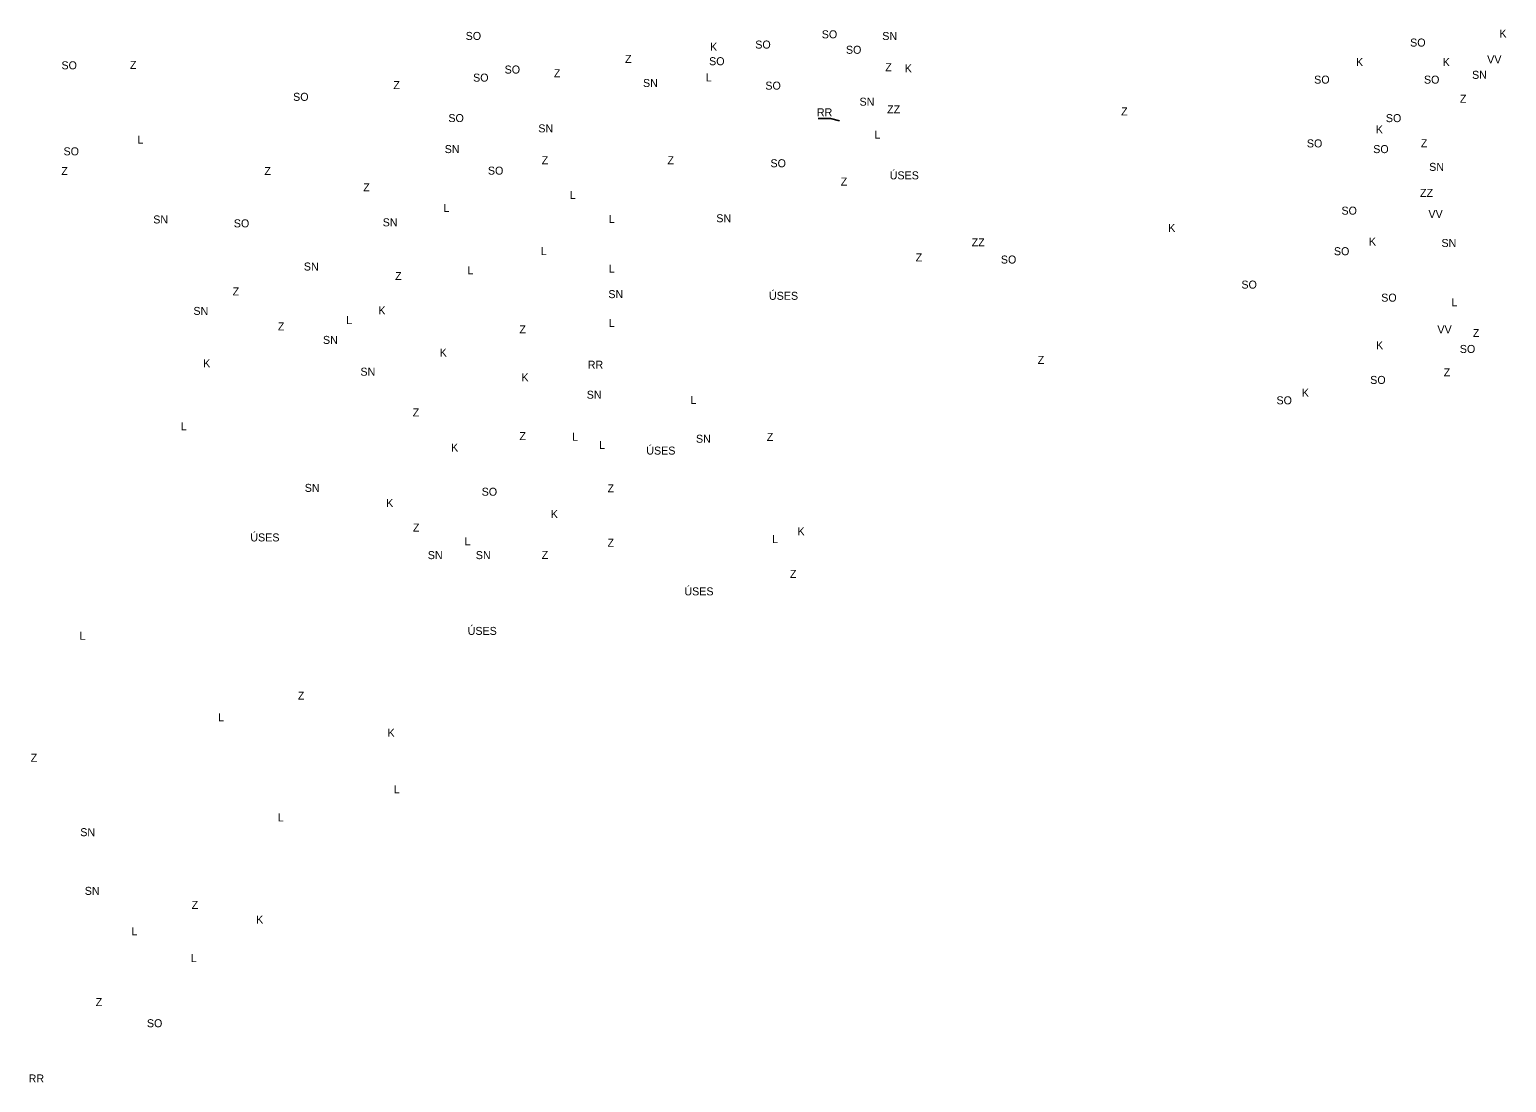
# Model space of a CAD drawing. Extents: x -445021 to -431236, y -1134464 to -1129615.
# Drawn here: x -443196 to -441350, y -1133478 to -1132163 of the extents above; entities that cross this region are included whole.
import ezdxf

# ---------------------------------------------------------------- set-up
doc = ezdxf.new("R2010")
doc.units = 0
doc.layers.add('Vrstva 84', color=7, linetype='Continuous')

msp = doc.modelspace()

# ---------------------------------------------------------------- linework, layer by layer
at = {"layer": 'Vrstva 84'}
msp.add_lwpolyline([(-442210.3, -1132274), (-442194.7, -1132274), (-442183.5, -1132276.8)], dxfattribs=at)

# ---------------------------------------------------------------- texts
for s, p in [('SO', (-442650.7, -1132175.9)), ('SO', (-442205.7, -1132173.9)), ('SN', (-442130.1, -1132176)), ('K', (-441358.9, -1132172.9)), ('K', (-442345.3, -1132189.5)), ('SO', (-442288.8, -1132186.7)), ('SO', (-442175.5, -1132193.2)), ('SO', (-441470.5, -1132184.2)), ('SO', (-443155.8, -1132212.6)), ('Z', (-443070.2, -1132212.1)), ('Z', (-442451.5, -1132204.6)), ('SO', (-442346.5, -1132207.5)), ('Z', (-442126.4, -1132215)), ('K', (-441538.1, -1132208.6)), ('K', (-441429.8, -1132208.6)), ('VV', (-441374.2, -1132205.3)), ('SO', (-442641.4, -1132228)), ('SO', (-442602, -1132217.9)), ('Z', (-442540.5, -1132222.5)), ('L', (-442350.7, -1132227.7)), ('K', (-442102, -1132216.5)), ('SO', (-441590.4, -1132230.5)), ('SO', (-441453.2, -1132230.5)), ('SN', (-441393.1, -1132224.5)), ('SO', (-442866.3, -1132252)), ('Z', (-442741, -1132237.3)), ('SN', (-442429.1, -1132234.7)), ('SO', (-442276.2, -1132238)), ('SN', (-442158.5, -1132258.1)), ('ZZ', (-442124, -1132267.6)), ('Z', (-441831.6, -1132270.2)), ('Z', (-441408.3, -1132254.4)), ('SO', (-442672.3, -1132278.5)), ('RR', (-442211.8, -1132271.4)), ('SO', (-441500.8, -1132278.6)), ('L', (-443060.8, -1132305.5)), ('SN', (-442559.9, -1132291.4)), ('L', (-442140, -1132299.3)), ('K', (-441513.3, -1132292.7)), ('SO', (-443153.2, -1132320.1)), ('SN', (-442676.9, -1132317.3)), ('SO', (-441599.5, -1132310.2)), ('SO', (-441516.6, -1132317.3)), ('Z', (-441457.1, -1132309.9)), ('Z', (-443156, -1132344.7)), ('Z', (-442902.2, -1132344.7)), ('SO', (-442622.9, -1132344.2)), ('Z', (-442555.7, -1132331.2)), ('Z', (-442398.5, -1132331.2)), ('SO', (-442269.8, -1132335)), ('SN', (-441446.7, -1132339.5)), ('Z', (-442182, -1132357.9)), ('ÚSES', (-442120.8, -1132350.1)), ('Z', (-442778.7, -1132365.1)), ('L', (-442520.6, -1132374.5)), ('ZZ', (-441458.1, -1132372)), ('L', (-442678.4, -1132390.8)), ('SO', (-441556.3, -1132394.2)), ('VV', (-441447.6, -1132398.4)), ('SN', (-443041.1, -1132405.2)), ('SO', (-442940.4, -1132410.1)), ('SN', (-442754.4, -1132408.8)), ('L', (-442471.7, -1132404.5)), ('SN', (-442337.5, -1132403.7)), ('K', (-441772.8, -1132415.8)), ('ZZ', (-442018.4, -1132433.8)), ('K', (-441522, -1132432.8)), ('SN', (-441431.3, -1132434.6)), ('L', (-442556.7, -1132444.7)), ('Z', (-442088.3, -1132452.6)), ('SO', (-441981.9, -1132455.3)), ('SO', (-441565.7, -1132444.9)), ('SN', (-442852.9, -1132464)), ('L', (-442648.4, -1132468.7)), ('L', (-442471.7, -1132466.6)), ('Z', (-442738.8, -1132475.8)), ('SO', (-441681.3, -1132486.6)), ('Z', (-442941.9, -1132495.2)), ('SN', (-442472.4, -1132498.5)), ('ÚSES', (-442271.7, -1132500.6)), ('SO', (-441506.6, -1132502.9)), ('L', (-441419, -1132508.8)), ('SN', (-442990.9, -1132519.5)), ('K', (-442759.8, -1132518.9)), ('Z', (-442885.4, -1132538.9)), ('L', (-442799.9, -1132531)), ('Z', (-442583.5, -1132542.5)), ('L', (-442471.7, -1132534.4)), ('VV', (-441436.4, -1132542.7)), ('Z', (-441392.1, -1132547.1)), ('SN', (-442829, -1132555.7)), ('K', (-441513.1, -1132562.4)), ('K', (-442683.2, -1132571.6)), ('Z', (-441935.9, -1132580.7)), ('SO', (-441408.4, -1132567)), ('K', (-442978.7, -1132585)), ('SN', (-442782.2, -1132595.4)), ('K', (-442581, -1132602.5)), ('RR', (-442498.1, -1132586.7)), ('Z', (-441428.5, -1132596.2)), ('K', (-441605.8, -1132621.7)), ('SO', (-441520.4, -1132605.7)), ('SN', (-442499.4, -1132624.2)), ('L', (-442369.8, -1132630.7)), ('SO', (-441637.5, -1132631.2)), ('Z', (-442716.9, -1132646.4)), ('L', (-443006.8, -1132663.7)), ('Z', (-442583.5, -1132675.9)), ('L', (-442517.7, -1132676.8)), ('Z', (-442274.4, -1132676.9)), ('K', (-442668.9, -1132690.2)), ('L', (-442484.1, -1132687)), ('ÚSES', (-442425, -1132694)), ('SN', (-442362.9, -1132679.2)), ('SN', (-442851.8, -1132740.6)), ('SO', (-442630.7, -1132745.4)), ('Z', (-442473.4, -1132741.2)), ('K', (-442750, -1132759.5)), ('K', (-442544.3, -1132773.3)), ('ÚSES', (-442919.8, -1132802.5)), ('Z', (-442716.6, -1132790.2)), ('L', (-442267.7, -1132804.6)), ('K', (-442236, -1132794.9)), ('SN', (-442698, -1132824.6)), ('L', (-442652, -1132807.2)), ('SN', (-442638, -1132824.6)), ('Z', (-442555.7, -1132824.3)), ('Z', (-442473.4, -1132809.2)), ('Z', (-442245.5, -1132848.1)), ('ÚSES', (-442377.4, -1132869.9)), ('ÚSES', (-442648.2, -1132919.3)), ('L', (-443133.1, -1132925.4)), ('Z', (-442860.4, -1133000.2)), ('L', (-442960, -1133027.2)), ('K', (-442748.3, -1133046.6)), ('Z', (-443194.2, -1133077.8)), ('L', (-442740.5, -1133117.3)), ('L', (-442885.6, -1133152.4)), ('SN', (-443132.3, -1133170.8)), ('SN', (-443126.7, -1133244.1)), ('Z', (-442993.1, -1133261.6)), ('K', (-442912.5, -1133280)), ('L', (-443068.4, -1133294.5)), ('L', (-442994.1, -1133328.1)), ('Z', (-443113, -1133383.1)), ('SO', (-443049, -1133409.5)), ('RR', (-443196.8, -1133478.5))]:
    msp.add_text(s, height=10, dxfattribs=at).set_placement(p)

doc.saveas('drawing.dxf')
